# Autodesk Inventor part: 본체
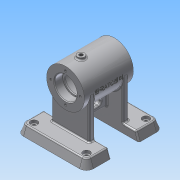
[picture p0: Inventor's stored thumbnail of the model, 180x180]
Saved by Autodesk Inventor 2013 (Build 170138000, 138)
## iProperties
Created: 2016-07
Part Number: 본체
Material: 알루미늄 6061
Document SubType Name: Modeling
Designer: mrc
Density: 2.71 g/cm^3
Mass: 499.419 g
Surface Area: 540.243 cm^2
Volume: 184.287 cm^3
Author: mrc
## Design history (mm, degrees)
sketch "스케치1"
  geometry: L1 (-35, 0)-(-35, 16); L2 (-35, 27)-(35, 27); L3 (35, 27)-(35, 17); L4 (35, 0)-(-35, 0); L5 (-34, 16)-(-23, 16); L6 (-23, 16)-(-23, 14); L7 (-23, 14)-(-21, 14); L8 (-21, 14)-(-21, 19); L9 (-18, 22)-(18, 22); L10 (21, 19)-(21, 14); L11 (21, 14)-(23, 14); L12 (23, 14)-(23, 16); L13 (23, 16)-(34, 16); L14 (-35, 17)-(-35, 27); L15 (35, 16)-(35, 0); L16 (-34, 16)-(-35, 17); L17 (34, 16)-(35, 17); A1 r 3 centre (-18, 19) between (-18, 22) and (-21, 19); A2 r 3 centre (18, 19) between (21, 19) and (18, 22); 3 further points
  constraints: 34 end point, 12 parallel, 5 perpendicular, 4 point on circle, 4 point on line, 4 tangent, 2 centre point, 2 midpoint, 2 vertical, 1 coincident, 1 equal radius, 1 vertical alignment
  dimensions: "d0" = 54 diameter of L2 L4; "d2" = 32 diameter of L13 L4; "d3" = 28 diameter of L11 L4; "d4" = 44 diameter of L9 L4; "d5" = 32 diameter of L5 L4; "d6" = 28 diameter of L7 L4; "d7" = 70 distance between parallel lines of L3 L1; "d8" = 12 distance between parallel lines of L3 L12; "d9" = 42 distance between parallel lines of L10 L8; "d10" = 12 distance between parallel lines of L1 L6; "d11" = 1 distance of L5.start L1.end; "d12" = 45 deg angle of L5 L16; "d13" = 1 distance of L13.end L15.start (= d11); "d14" = 45 deg angle of L13 L17 (= d12); "d15" = 3 radius of A1
revolve "회전1" sketch "스케치1" stored, may be unused: angle "d16" = 90 deg
node "작업 평면2"
  node "작업 평면1"
sketch "스케치2"
  geometry: L1 (-35, 27)-(-35, -27) reference; L2 (35, 27)-(35, -27) reference; C1 r 5 at (13, 0); 1 further point
  constraints: 1 centre point, 1 horizontal alignment
  dimensions: "d18" = 10 diameter of C1; "d19" = 22 distance from line of L2 C1.centre
extrude "돌출1" join sketch "스케치2" stored distance "d20" = 10; taper "d21" = 0 deg
hole "구멍1" diameter "d24" = 5.188; stored, may be unused: countersink angle "d28" = 90 deg, drill point angle "d30" = 0 deg; dims "d22" = 10, "d23" = 10, "d25" = 6, "d26" = 4, "d27" = 2, "d29" = 8
node "작업 평면4"
  node "작업 평면3"
sketch "스케치4"
  geometry: C1 r 27 at (0, 0) reference; 1 further point
  constraints: 1 vertical alignment
  dimensions: "d45" = 21 distance of C1.centre point (0, 21)
hole "구멍3" sketch "스케치4" at (0, 21) diameter "d46" = 3.242; stored, may be unused: countersink angle "d50" = 90 deg, drill point angle "d52" = 118 deg; dims "d47" = 8, "d48" = 4, "d49" = 2, "d51" = 10
fillet "모깎기1" dims "d56" = 2
node "작업 평면5"
sketch "스케치5"
  geometry: L1 (-45, -50)-(-20, -50); L2 (55, -40)-(55, 40); L3 (45, 50)-(20, 50); L4 (-55, 40)-(-55, -40); L5 (-55, -50)-(55, 50); L6 (55, -50)-(-55, 50); L7 (-20, -50)-(-20, 50); L8 (20, -50)-(20, 50); L9 (-20, -50)-(20, -50); L10 (20, -50)-(45, -50); L11 (-20, 50)-(-45, 50); L12 (20, 50)-(-20, 50); L13 (-55, 0)-(55, 0); A1 r 10 centre (-45, -40) between (-55, -40) and (-45, -50); A2 r 10 centre (-45, 40) between (-45, 50) and (-55, 40); A3 r 10 centre (45, 40) between (55, 40) and (45, 50); A4 r 10 centre (45, -40) between (45, -50) and (55, -40); 5 further points
  constraints: 26 end point, 10 parallel, 9 perpendicular, 9 point on line, 8 point on circle, 8 tangent, 7 midpoint, 4 centre point, 3 equal radius, 3 horizontal, 1 coincident
  dimensions: "d58" = 110 distance of L6.end L5.end; "d59" = 100 distance of L5.end L6.start; "d60" = 35 distance between parallel lines of L7 L4; "d61" = 35 distance between parallel lines of L2 L8; "d66" = 10 radius of A1
extrude "돌출3" join sketch "스케치5" distance "d67" = 12; taper "d68" = 0 deg
extrude "돌출4" cut sketch "스케치5" distance "d69" = 12; taper "d70" = 0 deg
sketch "스케치6"
  geometry: L1 (-20, -50)-(-20, 50) reference; L2 (-45, -50)-(-20, -50) reference; L3 (-28, 27)-(-28, -27); L4 (-28, -27)-(-20, -27); L5 (-28, 27)-(-20, 27); L6 (20, -50)-(20, 50) reference; L7 (20, 27)-(28, 27); L8 (28, 27)-(28, -27); L9 (28, -27)-(20, -27); 3 further points
  constraints: 12 end point, 6 perpendicular, 4 point on line, 2 horizontal alignment, 2 midpoint
  dimensions: "d71" = 8 distance between parallel lines of L1 L3; "d72" = 54 distance between parallel lines of L4 L5; "d73" = 8 distance between parallel lines of L6 L8; "d74" = 54 distance between parallel lines of L9 L7
extrude "돌출5" join sketch "스케치6" stored distance "d75" = 12; taper "d76" = 0 deg
sketch "스케치7"
  geometry: L1 (18, 22)-(-10.406, 22) reference; L2 (-10.406, 22)-(-10.406, 30) reference; L3 (-10.406, 30)-(-8, 30) reference; L4 (-8, 30)-(-8, 29) reference; L5 (-6, 27)-(35, 27) reference; L6 (35, 27)-(35, 22.621) reference; L7 (35, 22.621)-(25, 22.621) reference; L8 (25, 22.621)-(24.026, 21) reference; L9 (24.026, 21)-(25, 19.379) reference; L10 (25, 19.379)-(35, 19.379) reference; L11 (35, 19.379)-(35, 17) reference; L12 (35, 17)-(34, 16) reference; L13 (34, 16)-(23, 16) reference; L14 (23, 16)-(23, 14) reference; L15 (23, 14)-(21, 14) reference; L16 (21, 14)-(21, 19) reference; L17 (-15.594, 22)-(-18, 22) reference; L18 (-21, 19)-(-21, 14) reference; L19 (-21, 14)-(-23, 14) reference; L20 (-23, 14)-(-23, 16) reference; L21 (-23, 16)-(-34, 16) reference; L22 (-34, 16)-(-35, 17) reference; L23 (-35, 17)-(-35, 19.379) reference; L24 (-35, 19.379)-(-25, 19.379) reference; L25 (-25, 19.379)-(-24.026, 21) reference; L26 (-24.026, 21)-(-25, 22.621) reference; L27 (-25, 22.621)-(-35, 22.621) reference; L28 (-35, 22.621)-(-35, 27) reference; L29 (-35, 27)-(-20, 27) reference; L30 (-18, 29)-(-18, 30) reference; L31 (-18, 30)-(-15.594, 30) reference; L32 (-15.594, 30)-(-15.594, 22) reference; L33 (-18, -22)-(18, -22) reference; L34 (21, -19)-(21, -14) reference; L35 (21, -14)-(23, -14) reference; L36 (23, -14)-(23, -16) reference; L37 (23, -16)-(34, -16) reference; L38 (34, -16)-(35, -17) reference; L39 (35, -17)-(35, -19.379) reference; L40 (35, -19.379)-(25, -19.379) reference; L41 (25, -19.379)-(24.026, -21) reference; L42 (24.026, -21)-(25, -22.621) reference; L43 (25, -22.621)-(35, -22.621) reference; L44 (35, -22.621)-(35, -27) reference; L45 (35, -27)-(28, -27) reference; L46 (28, -27)-(28, -58) reference; L47 (28, -58)-(55, -58) reference; L48 (55, -58)-(55, -70) reference; L49 (55, -70)-(20, -70) reference; L50 (20, -70)-(20, -27) reference; L51 (20, -27)-(-20, -27) reference; L52 (-20, -27)-(-20, -70) reference; L53 (-20, -70)-(-55, -70) reference; L54 (-55, -70)-(-55, -58) reference; L55 (-55, -58)-(-28, -58) reference; L56 (-28, -58)-(-28, -27) reference; L57 (-28, -27)-(-35, -27) reference; L58 (-35, -27)-(-35, -22.621) reference; L59 (-35, -22.621)-(-25, -22.621) reference; L60 (-25, -22.621)-(-24.026, -21) reference; L61 (-24.026, -21)-(-25, -19.379) reference; L62 (-25, -19.379)-(-35, -19.379) reference; L63 (-35, -19.379)-(-35, -17) reference; L64 (-35, -17)-(-34, -16) reference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; A1 r 3 centre (18, 19) between (21, 19) and (18, 22) reference; A2 r 3 centre (-18, 19) between (-18, 22) and (-21, 19) reference; A3 r 3 centre (18, -19) between (18, -22) and (21, -19) reference; A4 r 3 centre (-18, -19) between (-21, -19) and (-18, -22) reference; A5 r 3.5 centre (8, -38) between (8, -41.5) and (8, -34.5); A6 r 3.5 centre (-8, -38) between (-8, -34.5) and (-8, -41.5); 2 further points
  constraints: 6 end point, 4 point on circle, 4 tangent, 2 centre point, 2 parallel, 2 point on line, 1 midpoint, 1 perpendicular, 1 vertical alignment, 2 other
  dimensions: "d77" = 21 distance between parallel lines of L69 L51; "d78" = 23 dimension on A5 A6; "d79" = 3.5 radius of A5; "d80" = 32 distance from line of L49 A5.centre
  node "절단 모서리 투영1"
feature "리브1" dims "d81" = 1, "d82" = 8, "d83" = 0, "d84" = 0, "d85" = 1, "d86" = 1
extrude "돌출6" cut sketch "스케치7" stored distance "d87" = 50; taper "d88" = 0 deg
sketch "스케치8"
  geometry: L1 (20, -50)-(20, 50) reference; L2 (20, 50)-(45, 50) reference; L3 (55, 40)-(55, -40) reference; L4 (45, -50)-(20, -50) reference; L5 (-45, 50)-(-20, 50) reference; L6 (-20, 50)-(-20, -50) reference; L7 (-20, -50)-(-45, -50) reference; L8 (-55, -40)-(-55, 40) reference; L9 (-42.5, 37.5)-(42.5, 37.5); L10 (42.5, 37.5)-(42.5, -37.5); L11 (42.5, -37.5)-(-42.5, -37.5); L12 (-42.5, -37.5)-(-42.5, 37.5); L13 (-42.5, 37.5)-(42.5, -37.5); L14 (42.5, 37.5)-(-42.5, -37.5); A1 r 10 centre (45, 40) between (55, 40) and (45, 50) reference; A2 r 10 centre (45, -40) between (45, -50) and (55, -40) reference; A3 r 10 centre (-45, -40) between (-55, -40) and (-45, -50) reference; A4 r 10 centre (-45, 40) between (-45, 50) and (-55, 40) reference; 5 further points
  constraints: 12 end point, 4 coincident, 2 midpoint, 2 parallel, 1 horizontal, 1 perpendicular
  dimensions: "d89" = 85 distance of L10.end L11.end; "d90" = 75 distance of L9.end L10.end
hole "구멍4" sketch "스케치8" at (-42.5, 37.5), (-42.5, -37.5), (42.5, -37.5), (42.5, 37.5) diameter "d91" = 6; stored, may be unused: countersink angle "d95" = 90 deg, drill point angle "d97" = 0 deg; dims "d92" = 8, "d93" = 4, "d94" = 2, "d96" = 12
hole "구멍5" diameter "d100" = 10; stored, may be unused: countersink angle "d104" = 90 deg, drill point angle "d106" = 0 deg; dims "d98" = 10, "d99" = 10, "d101" = 8, "d102" = 4, "d103" = 2, "d105" = 4
hole "구멍6" diameter "d109" = 10; stored, may be unused: countersink angle "d113" = 90 deg, drill point angle "d115" = 0 deg; dims "d107" = 10, "d108" = 10, "d110" = 8, "d111" = 4, "d112" = 2, "d114" = 4
hole "구멍7" diameter "d118" = 10; stored, may be unused: countersink angle "d122" = 90 deg, drill point angle "d124" = 0 deg; dims "d116" = 10, "d117" = 10, "d119" = 8, "d120" = 4, "d121" = 2, "d123" = 4
hole "구멍8" diameter "d127" = 10; stored, may be unused: countersink angle "d131" = 90 deg, drill point angle "d133" = 0 deg; dims "d125" = 10, "d126" = 10, "d128" = 8, "d129" = 4, "d130" = 2, "d132" = 4
fillet "모깎기2" dims "d134" = 2
feature "면 기울기1" dims angle "d135" = 20 deg
sketch "스케치9"
  geometry: L1 (26, 29)-(20, 29) reference; L2 (30, -25)-(30, 25) reference; L3 (20, -29)-(26, -29) reference; L4 (20, -29)-(20, -45.632) reference; L5 (20, -45.632)-(45, -45.632) reference; L6 (50.632, -40)-(50.632, 40) reference; L7 (45, 45.632)-(20, 45.632) reference; L8 (20, 45.632)-(20, 29) reference; C1 r 5 at (42.5, -37.5) reference; C2 r 5 at (42.5, 37.5) reference; A1 r 4 centre (26, 25) between (30, 25) and (26, 29) reference; A2 r 4 centre (26, -25) between (26, -29) and (30, -25) reference; A3 r 5.632 centre (45, -40) between (45, -45.632) and (50.632, -40) reference; A4 r 5.632 centre (45, 40) between (50.632, 40) and (45, 45.632) reference; 1 further point
feature "면 기울기2" dims angle "d136" = 20 deg
fillet "모깎기3" dims "d137" = 2
fillet "모깎기4" dims "d138" = 2
fillet "모깎기5" dims "d139" = 2
fillet "모깎기6" dims "d140" = 2
fillet "모깎기7" dims "d141" = 2
node "작업 평면6"
sketch "스케치10"
  geometry: L1 (-35, 27)-(35, 27) reference; 2 further points
  constraints: 1 coincident, 1 other
feature "엠보싱1" sketch "스케치10" dims "d13" = 1 (= d11), "d142" = 0.5, "d143" = 0
node "작업 평면8"
  node "작업 평면7"
sketch "스케치11"
  geometry: C1 r 6 at (0, 0); 1 further point
  constraints: 1 centre point, 1 coincident
  dimensions: "d146" = 12 diameter of C1
extrude "돌출7" join sketch "스케치11" stored distance "d147" = 50; taper "d148" = 0 deg
hole "구멍9" diameter "d151" = 5.188; stored, may be unused: countersink angle "d155" = 90 deg, drill point angle "d157" = 0 deg; dims "d149" = 10, "d150" = 10, "d152" = 8, "d153" = 4, "d154" = 2, "d156" = 4
fillet "모깎기8" dims "d158" = 2
fillet "모깎기9" dims "d159" = 0.3
fillet "모깎기10" dims "d160" = 0.3
node "솔리드1"
pattern_circular "원형 패턴1" dims angle "d54" = 360 deg
mirror "대칭1"
node "투영된 루프1"
node "절단 모서리 투영2"
other parameters: "d17" = 3, "d31" = 58 deg, "d144" = -58 deg
